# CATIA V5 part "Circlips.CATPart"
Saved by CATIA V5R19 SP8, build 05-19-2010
Part number: Circlips
Publications: "Rayon_ext", "Rayon_int"
Bounding box of the stored display mesh (mm): x -13.427 to 13.427, y -16 to 13.321, z 0 to 1
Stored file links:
  F:\! CONCEPTION\PROJET\Mécanisme 590\CAO\Circlips.CATPart
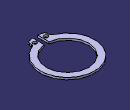
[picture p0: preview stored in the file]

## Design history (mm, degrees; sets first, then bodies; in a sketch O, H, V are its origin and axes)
Parameters
  Rayon_ext = 13.5 mm {= Rayon_int +3mm}
  Rayon_int = 10.5 mm
Body1 (main body)
  Sketch1 on xy-plane, origin (0, 0, 0), H (1, 0, 0), V (0, 1, 0)
    arc A1 centre (0, 0) radius 13.5 from (4.8879, -12.584) to (-4.8879, -12.584) ccw
    point P1 (0, 0)
    arc A2 centre (0, 0) radius 10.5 from (1.25, -10.4253) to (-1.25, -10.4253) ccw
    point P2 (0, 0)
    line L1 (-1.25, -10.4253) -> (-1.25, -16)
    point P3 (-1.25, -16)
    line L2 (-1.25, -16) -> (-3.4236, -15.6167)
    line L3 (-4.25, -14.6319) -> (-4.25, -13.5162)
    line L4 (1.25, -10.4253) -> (1.25, -16)
    line L5 (1.25, -16) -> (3.4236, -15.6167)
    line L6 (4.25, -14.6319) -> (4.25, -13.5162)
    arc A3 centre (-3.25, -14.6319) radius 1 from (-4.25, -14.6319) to (-3.4236, -15.6167) ccw
    arc A4 centre (3.25, -14.6319) radius 1 from (4.25, -14.6319) to (3.4236, -15.6167) cw
    arc A5 centre (5.25, -13.5162) radius 1 from (4.8879, -12.584) to (4.25, -13.5162) ccw
    arc A6 centre (-5.25, -13.5162) radius 1 from (-4.8879, -12.584) to (-4.25, -13.5162) cw
    circle A7 centre (2.75, -13.5) radius 1
    point P20 (-2.75, -13.5)
    circle A8 centre (-2.75, -13.5) radius 1
    radius A1 = 13.5 {= Rayon_ext}
    radius A2 = 10.5 {= Rayon_int}
    radius A3 = 1
    radius A4 = 1
    radius A5 = 1
    radius A6 = 1
    distance L1 L4 = 2.5
    distance L3 L1 = 3
    distance P20 L1 = 1.5
    radius A8 = 1
    distance P3 H = 16 {= Rayon_ext +2.5mm}
    angle L5 H = 10
    distance P20 H = 13.5 {= Rayon_ext}
    vertical: L1 V, L3 V, L4 V, L6 V
    symmetry: L6 L3 V, L1 L4 V, L5 L2 V, A8 A7 V
    tangency: A3 L3, A3 L2, A4 L6, A4 L5, A5 L6, A5 A1, A6 A1, A6 L3
    coincidence: P1 O, P2 V, P2 H
  Pad1: profile Sketch1, direction (0, 0, 1), length 1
